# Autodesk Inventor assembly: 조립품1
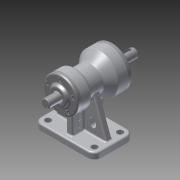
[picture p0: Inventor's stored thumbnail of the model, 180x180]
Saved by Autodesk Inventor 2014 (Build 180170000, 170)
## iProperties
Created: 2015-08
Part Number: 조립품1
Document SubType Name: Assembly
Designer: SCD-A08
Author: SCD-A08
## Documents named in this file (10)
- C:\Users\SCD-A08\Desktop\450805V1020\조립품1.iam
- C:\Users\SCD-A08\Desktop\450805V1020\부품1.ipt
- C:\Users\SCD-A08\Desktop\450805V1020\베어링 6203.ipt
- C:\Users\SCD-A08\Desktop\450805V1020\베어링 6205.ipt
- C:\Users\SCD-A08\Desktop\450805V1020\축.ipt
- C:\Users\SCD-A08\Desktop\450805V1020\뒤커버.ipt
- C:\Users\SCD-A08\Desktop\450805V1020\앞커버.ipt
- C:\Users\SCD-A08\Desktop\450805V1020\오일실 .ipt
- 오일실 .ipt
- C:\Users\SCD-A08\Desktop\450805V1020\M4x0.5.ipt
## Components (10 placed, 1 different names)
1. M4x0.5:1
2. M4x0.5:2
3. M4x0.5:3
4. M4x0.5:4
5. M4x0.5:5
6. M4x0.5:6
7. M4x0.5:7
8. M4x0.5:8
9. M4x0.5:9
10. M4x0.5:10
